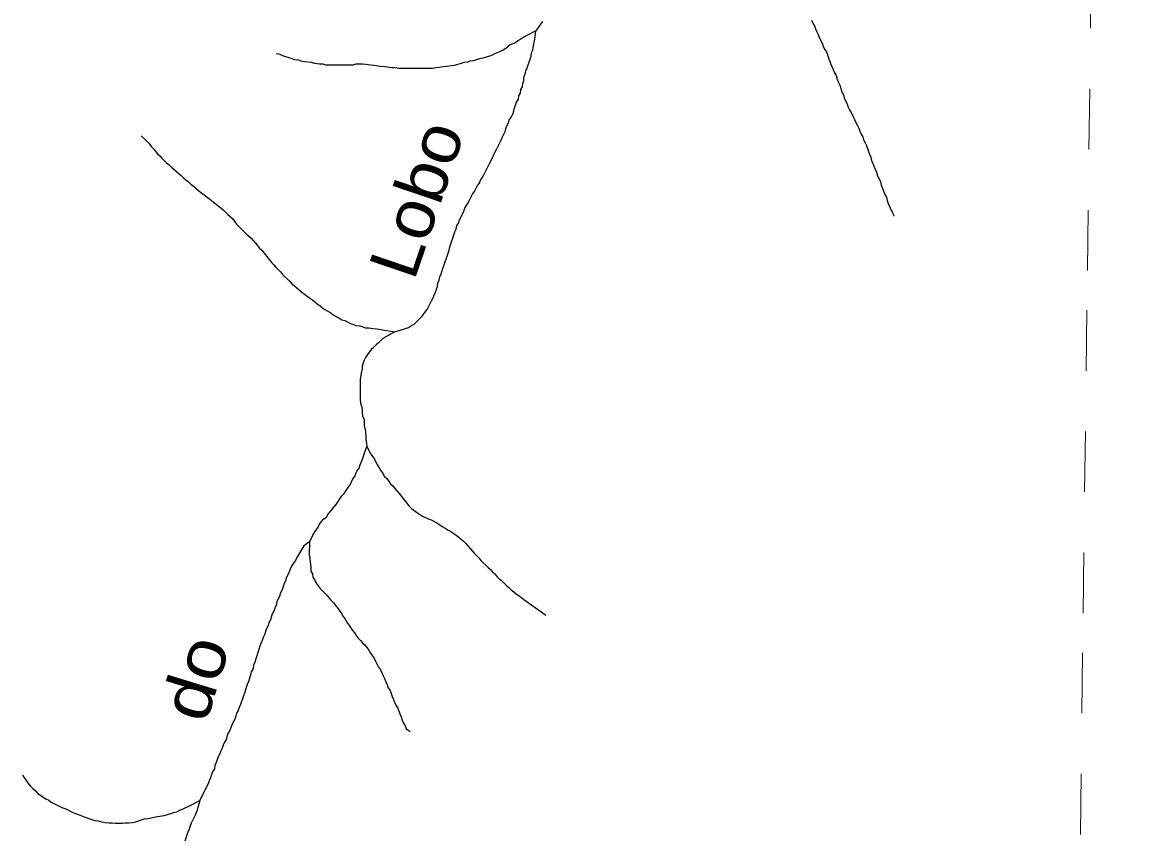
# Model space of a CAD drawing. Extents: x 652.3 to 678, y 7316.9 to 7344.9.
# Drawn here: x 675.947 to 677.802, y 7318.266 to 7319.614 of the extents above; entities that cross this region are included whole.
import ezdxf
from ezdxf.enums import TextEntityAlignment as Align

# ---------------------------------------------------------------- set-up
doc = ezdxf.new("R2010")
doc.units = 0
doc.header["$LTSCALE"] = 0.032
doc.linetypes.add('SHORT_DASHED', pattern=[2.7, 1.5, -1.2])
doc.layers.add('53', color=7, linetype='SHORT_DASHED', lineweight=13)
doc.layers.add('7', color=7, linetype='Continuous', lineweight=25)
doc.layers.add('61', color=7, linetype='Continuous')

msp = doc.modelspace()

# ---------------------------------------------------------------- linework, layer by layer
at = {"layer": '53'}
msp.add_lwpolyline([(677.6746, 7316.9441), (677.6817, 7317.5092), (677.6888, 7318.0742), (677.6959, 7318.6393), (677.703, 7319.2044), (677.7101, 7319.7694), (677.7172, 7320.3345), (677.7242, 7320.8996), (677.7313, 7321.4647), (677.7384, 7322.0297), (677.7455, 7322.5948), (677.7526, 7323.1599), (677.7596, 7323.7249), (677.7667, 7324.29), (677.7738, 7324.8551), (677.7808, 7325.4201), (677.7879, 7325.9852), (677.795, 7326.5503), (677.802, 7327.1153)], dxfattribs=at)
at = {"layer": '7'}
msp.add_line((676.4206, 7318.7344), (676.4214, 7318.7574), dxfattribs=at)
for points in [[(676.8049, 7319.6152), (676.7938, 7319.6001)], [(677.2481, 7319.6176), (677.2505, 7319.6128), (677.2529, 7319.608), (677.2545, 7319.6032), (677.2569, 7319.5985), (677.2593, 7319.5937), (677.2609, 7319.5889), (677.2656, 7319.5794), (677.2672, 7319.5746), (677.2696, 7319.5698), (677.2728, 7319.5651), (677.2744, 7319.5603), (677.276, 7319.5555), (677.2792, 7319.546), (677.2815, 7319.5412), (677.2839, 7319.5364), (677.2855, 7319.5316), (677.2887, 7319.5261), (677.2903, 7319.5205), (677.2919, 7319.5157), (677.2951, 7319.5101), (677.2967, 7319.5046), (677.2982, 7319.499), (677.3006, 7319.4942), (677.3022, 7319.4887), (677.3046, 7319.4839), (677.307, 7319.4791), (677.3086, 7319.4743), (677.311, 7319.4696), (677.3142, 7319.464), (677.3166, 7319.4584), (677.3189, 7319.4537), (677.3213, 7319.4489), (677.3237, 7319.4441), (677.3261, 7319.4393), (677.3277, 7319.4346), (677.3301, 7319.4298), (677.3325, 7319.425), (677.3341, 7319.4202), (677.3364, 7319.4155), (677.3388, 7319.4107), (677.342, 7319.4011), (677.3436, 7319.3964), (677.346, 7319.3916), (677.3468, 7319.386), (677.3492, 7319.3812), (677.3508, 7319.3765), (677.3555, 7319.3669), (677.3571, 7319.3606), (677.3595, 7319.3558), (677.3619, 7319.351), (677.3627, 7319.3454), (677.3651, 7319.3407), (677.3683, 7319.3311), (677.3715, 7319.3255), (677.373, 7319.32), (677.3746, 7319.3152), (677.381, 7319.3009), (677.3836, 7319.2951), (677.3839, 7319.2943)], [(676.7938, 7319.6001), (676.7787, 7319.5921), (676.7739, 7319.5897), (676.7691, 7319.5865), (676.7643, 7319.5834), (676.7604, 7319.5802), (676.7516, 7319.577), (676.7445, 7319.5706), (676.7397, 7319.5682), (676.7301, 7319.5635), (676.7254, 7319.5619), (676.7206, 7319.5595), (676.7158, 7319.5579), (676.7063, 7319.5547), (676.7007, 7319.5539), (676.6911, 7319.5507), (676.6856, 7319.5499), (676.6808, 7319.5483), (676.6752, 7319.5475), (676.6705, 7319.546), (676.6593, 7319.5428), (676.6466, 7319.5412), (676.641, 7319.5404), (676.6346, 7319.5396), (676.6291, 7319.5388), (676.6235, 7319.538), (676.5678, 7319.538), (676.5614, 7319.5388), (676.5559, 7319.5388), (676.5447, 7319.5404), (676.5376, 7319.5412), (676.5264, 7319.5428), (676.5209, 7319.5436), (676.5137, 7319.5444), (676.5081, 7319.5452), (676.497, 7319.5452), (676.4922, 7319.5436), (676.4477, 7319.5436), (676.4429, 7319.5452), (676.4373, 7319.5452), (676.4294, 7319.546), (676.4238, 7319.5475), (676.4126, 7319.5491), (676.4071, 7319.5499), (676.4023, 7319.5515), (676.3967, 7319.5523), (676.392, 7319.5539), (676.3872, 7319.5555), (676.3816, 7319.5571), (676.3768, 7319.5587), (676.3721, 7319.5611), (676.3665, 7319.5619), (676.3661, 7319.5619)], [(676.5614, 7319.1036), (676.5789, 7319.1091), (676.5837, 7319.1107), (676.5885, 7319.1139), (676.5933, 7319.1163), (676.6052, 7319.1282), (676.6148, 7319.1402), (676.6219, 7319.1545), (676.6243, 7319.1593), (676.6259, 7319.164), (676.6283, 7319.1688), (676.6299, 7319.1736), (676.6315, 7319.1783), (676.6323, 7319.1839), (676.6346, 7319.1887), (676.6354, 7319.1943), (676.6378, 7319.199), (676.6394, 7319.2046), (676.641, 7319.2094), (676.6426, 7319.2142), (676.6474, 7319.2285), (676.649, 7319.2332), (676.6506, 7319.238), (676.6522, 7319.2436), (676.6537, 7319.2484), (676.6585, 7319.2627), (676.6601, 7319.2683), (676.6625, 7319.273), (676.6633, 7319.2786), (676.6665, 7319.2834), (676.6681, 7319.2882), (676.6705, 7319.2929), (676.6752, 7319.3025), (676.6768, 7319.3072), (676.6792, 7319.312), (676.6824, 7319.316), (676.6895, 7319.3303), (676.6927, 7319.3351), (676.6975, 7319.3446), (676.7007, 7319.3486), (676.7023, 7319.3534), (676.7055, 7319.3574), (676.7078, 7319.3622), (676.7102, 7319.3669), (676.7174, 7319.3812), (676.7198, 7319.386), (676.7269, 7319.4003), (676.7293, 7319.4051), (676.7365, 7319.4194), (676.7381, 7319.4242), (676.7429, 7319.4338), (676.7445, 7319.4385), (676.746, 7319.4433), (676.7484, 7319.4481), (676.75, 7319.4529), (676.7532, 7319.4576), (676.7556, 7319.4624), (676.7572, 7319.468), (676.7588, 7319.4728), (676.7604, 7319.4775), (676.762, 7319.4823), (676.7651, 7319.4871), (676.7659, 7319.4926), (676.7683, 7319.4974), (676.7691, 7319.503), (676.7715, 7319.5078), (676.7723, 7319.5133), (676.7739, 7319.5181), (676.7739, 7319.5237), (676.7763, 7319.5285), (676.7771, 7319.534), (676.7795, 7319.5388), (676.7842, 7319.5531), (676.7858, 7319.5579), (676.7866, 7319.5635), (676.789, 7319.5682), (676.7906, 7319.5786), (676.7922, 7319.5865), (676.7938, 7319.6001)], [(676.1435, 7319.4268), (676.1438, 7319.4265), (676.1517, 7319.4186), (676.1525, 7319.4178), (676.1564, 7319.4139), (676.1596, 7319.4091), (676.1636, 7319.4051), (676.17, 7319.3972), (676.1739, 7319.394), (676.1771, 7319.39), (676.1811, 7319.386), (676.1851, 7319.382), (676.1891, 7319.3789), (676.193, 7319.3749), (676.197, 7319.3717), (676.201, 7319.3685), (676.205, 7319.3645), (676.209, 7319.3614), (676.2129, 7319.3574), (676.2169, 7319.3542), (676.2209, 7319.351), (676.2249, 7319.347), (676.2296, 7319.3439), (676.2336, 7319.3399), (676.2376, 7319.3367), (676.2416, 7319.3335), (676.2456, 7319.3303), (676.2495, 7319.3271), (676.2543, 7319.324), (676.2583, 7319.3208), (676.2623, 7319.3176), (676.2662, 7319.3144), (676.2702, 7319.3112), (676.2742, 7319.308), (676.2782, 7319.3049), (676.2822, 7319.3009), (676.2861, 7319.2969), (676.2901, 7319.2937), (676.2941, 7319.2897), (676.2973, 7319.285), (676.3005, 7319.281), (676.3124, 7319.2691), (676.3164, 7319.2651), (676.3203, 7319.2619), (676.3243, 7319.2579), (676.3275, 7319.2539), (676.3315, 7319.25), (676.3347, 7319.246), (676.3379, 7319.242), (676.3418, 7319.238), (676.3577, 7319.2181), (676.3617, 7319.2142), (676.3649, 7319.2102), (676.3729, 7319.2022), (676.376, 7319.1982), (676.388, 7319.1863), (676.392, 7319.1823), (676.3959, 7319.1791), (676.3999, 7319.176), (676.4039, 7319.172), (676.4079, 7319.1688), (676.4126, 7319.1656), (676.4166, 7319.1624), (676.4206, 7319.1593), (676.4254, 7319.1561), (676.4294, 7319.1529), (676.4333, 7319.1497), (676.4381, 7319.1465), (676.4421, 7319.1433), (676.4461, 7319.1402), (676.4508, 7319.1378), (676.4556, 7319.1346), (676.4596, 7319.1314), (676.4644, 7319.129), (676.4691, 7319.1266), (676.4739, 7319.1234), (676.4787, 7319.1219), (676.4882, 7319.1171), (676.4978, 7319.1139), (676.5034, 7319.1131), (676.5129, 7319.1099), (676.5185, 7319.1099), (676.5248, 7319.1091), (676.532, 7319.1083), (676.5408, 7319.1067), (676.5614, 7319.1036)], [(676.5614, 7319.1036), (676.5416, 7319.0924), (676.5344, 7319.0853), (676.5304, 7319.0821), (676.5264, 7319.0781), (676.5225, 7319.0741), (676.5161, 7319.0662), (676.5129, 7319.0614), (676.5105, 7319.0566), (676.5073, 7319.0471), (676.5073, 7319.0415), (676.5057, 7319.0359), (676.5042, 7319.0248), (676.5042, 7318.9914), (676.5049, 7318.9858), (676.5065, 7318.981), (676.5073, 7318.9754), (676.5073, 7318.9699), (676.5081, 7318.9643), (676.5105, 7318.9595), (676.5105, 7318.9484), (676.5121, 7318.9428), (676.5137, 7318.9317), (676.5137, 7318.9261), (676.5145, 7318.9197), (676.5153, 7318.9142)], [(676.4214, 7318.7574), (676.4262, 7318.7678), (676.4286, 7318.7725), (676.4317, 7318.7765), (676.4349, 7318.7813), (676.4373, 7318.7861), (676.4405, 7318.7908), (676.4445, 7318.7948), (676.4485, 7318.798), (676.4516, 7318.8028), (676.4548, 7318.8068), (676.458, 7318.8107), (676.4644, 7318.8187), (676.4676, 7318.8235), (676.4707, 7318.8282), (676.4739, 7318.833), (676.4779, 7318.837), (676.4843, 7318.8465), (676.4874, 7318.8513), (676.4922, 7318.8609), (676.4954, 7318.8648), (676.497, 7318.8696), (676.4994, 7318.8744), (676.5026, 7318.8784), (676.5042, 7318.8839), (676.5081, 7318.8935), (676.5105, 7318.9014), (676.5153, 7318.9142)], [(676.5153, 7318.9142), (676.5217, 7318.9014), (676.528, 7318.8935), (676.532, 7318.8839), (676.5352, 7318.8792), (676.5384, 7318.8744), (676.5416, 7318.8704), (676.5439, 7318.8656), (676.5479, 7318.8617), (676.5511, 7318.8577), (676.5543, 7318.8529), (676.5583, 7318.8489), (676.5614, 7318.845), (676.5646, 7318.841), (676.5686, 7318.837), (676.5813, 7318.8211), (676.5845, 7318.8163), (676.5885, 7318.8123), (676.5925, 7318.8091), (676.5972, 7318.806), (676.602, 7318.8028), (676.6068, 7318.7996), (676.6163, 7318.7948), (676.6211, 7318.7932), (676.6307, 7318.7885), (676.6354, 7318.7853), (676.6394, 7318.7821), (676.6442, 7318.7797), (676.649, 7318.7765), (676.6537, 7318.7741), (676.6585, 7318.771), (676.6625, 7318.7678), (676.6665, 7318.7646), (676.6705, 7318.7614), (676.6744, 7318.7582), (676.6784, 7318.7542), (676.6816, 7318.7503), (676.6856, 7318.7463), (676.6919, 7318.7383), (676.6959, 7318.7344), (676.6999, 7318.7304), (676.7031, 7318.7264), (676.715, 7318.7145), (676.719, 7318.7113), (676.7222, 7318.7073), (676.7261, 7318.7041), (676.7293, 7318.7001), (676.7333, 7318.6962), (676.7373, 7318.693), (676.7452, 7318.685), (676.7492, 7318.6818), (676.7532, 7318.6779), (676.7572, 7318.6747), (676.7612, 7318.6715), (676.7651, 7318.6683), (676.7699, 7318.6651), (676.7739, 7318.6619), (676.8017, 7318.6421), (676.8102, 7318.636)], [(676.4214, 7318.7574), (676.4111, 7318.7503), (676.4063, 7318.7423), (676.3999, 7318.7312), (676.3975, 7318.7264), (676.3943, 7318.7216), (676.3912, 7318.7168), (676.3888, 7318.7121), (676.3872, 7318.7073), (676.3848, 7318.7025), (676.3824, 7318.6978), (676.3808, 7318.6922), (676.3784, 7318.6874), (676.3753, 7318.6779), (676.3729, 7318.6731), (676.3713, 7318.6675), (676.3665, 7318.658), (676.3657, 7318.6524), (676.3633, 7318.6476), (676.3617, 7318.6428), (676.3593, 7318.6381), (676.3562, 7318.6285), (676.3538, 7318.6238), (676.3522, 7318.619), (676.3498, 7318.6142), (676.3482, 7318.6094), (676.3466, 7318.6039), (676.3442, 7318.5991), (676.3426, 7318.5943), (676.3402, 7318.5895), (676.3386, 7318.5848), (676.3371, 7318.5792), (676.3355, 7318.5744), (676.3339, 7318.5689), (676.3323, 7318.5641), (676.3307, 7318.5585), (676.3283, 7318.5537), (676.3275, 7318.5482), (676.3243, 7318.5426), (676.3235, 7318.537), (676.3219, 7318.5322), (676.3203, 7318.5267), (676.318, 7318.5219), (676.3132, 7318.5076), (676.3116, 7318.5028), (676.3068, 7318.4885), (676.3044, 7318.4837), (676.3028, 7318.4789), (676.3005, 7318.4742), (676.2989, 7318.4694), (676.2973, 7318.4646), (676.2925, 7318.4551), (676.2909, 7318.4503), (676.2885, 7318.4455), (676.2861, 7318.4407), (676.283, 7318.4312), (676.2806, 7318.4264), (676.2782, 7318.4216), (676.2766, 7318.4169), (676.2742, 7318.4121), (676.2726, 7318.4073), (676.2702, 7318.4026), (676.267, 7318.393), (676.2647, 7318.3882), (676.2639, 7318.3827), (676.2607, 7318.3779), (676.2591, 7318.3731), (676.2575, 7318.3675), (676.2551, 7318.3628), (676.2535, 7318.358), (676.2487, 7318.3484), (676.24, 7318.3301)], [(676.4206, 7318.7344), (676.423, 7318.7145), (676.423, 7318.7089), (676.4254, 7318.7041), (676.4262, 7318.6985), (676.4294, 7318.6938), (676.4317, 7318.689), (676.4349, 7318.6842), (676.4381, 7318.6802), (676.45, 7318.6683), (676.4532, 7318.6643), (676.4564, 7318.6604), (676.4604, 7318.6564), (676.4668, 7318.6484), (676.4731, 7318.6389), (676.4763, 7318.6341), (676.4795, 7318.6293), (676.4819, 7318.6245), (676.4851, 7318.6206), (676.4882, 7318.6158), (676.4914, 7318.611), (676.4946, 7318.607), (676.4978, 7318.6023), (676.501, 7318.5983), (676.5049, 7318.5943), (676.5081, 7318.5903), (676.5121, 7318.5864), (676.5185, 7318.5784), (676.5209, 7318.5736), (676.524, 7318.5696), (676.5272, 7318.5649), (676.5296, 7318.5601), (676.5344, 7318.5505), (676.5376, 7318.5458), (676.54, 7318.541), (676.5423, 7318.5362), (676.5447, 7318.5307), (676.5463, 7318.5259), (676.5487, 7318.5211), (676.5503, 7318.5163), (676.5535, 7318.5116), (676.5551, 7318.5068), (676.5567, 7318.502), (676.5591, 7318.4972), (676.5606, 7318.4925), (676.563, 7318.4877), (676.5662, 7318.4829), (676.5694, 7318.4734), (676.5718, 7318.4686), (676.5734, 7318.463), (676.5758, 7318.4582), (676.5782, 7318.4535), (676.5797, 7318.4487), (676.5861, 7318.4447), (676.5864, 7318.4445)], [(675.9475, 7318.372), (675.9535, 7318.3636), (675.9575, 7318.358), (675.9607, 7318.354), (675.9647, 7318.35), (675.9687, 7318.3461), (675.9726, 7318.3421), (675.9774, 7318.3389), (675.9814, 7318.3357), (675.9862, 7318.3333), (675.9909, 7318.3309), (675.9949, 7318.3278), (676.0092, 7318.3206), (676.014, 7318.3182), (676.0188, 7318.3166), (676.0236, 7318.3142), (676.0283, 7318.3118), (676.0331, 7318.3095), (676.0379, 7318.3079), (676.0427, 7318.3063), (676.0474, 7318.3039), (676.0617, 7318.2991), (676.0665, 7318.2975), (676.0721, 7318.2967), (676.0777, 7318.2951), (676.084, 7318.2943), (676.0896, 7318.2935), (676.0952, 7318.2935), (676.1007, 7318.2927), (676.1119, 7318.2927), (676.1174, 7318.2935), (676.123, 7318.2935), (676.1286, 7318.2943), (676.1342, 7318.2951), (676.1389, 7318.2967), (676.1485, 7318.2999), (676.154, 7318.3007), (676.1596, 7318.3015), (676.1644, 7318.3031), (676.17, 7318.3039), (676.1811, 7318.3055), (676.1922, 7318.3087), (676.197, 7318.3103), (676.2018, 7318.3118), (676.2066, 7318.3142), (676.2137, 7318.3174), (676.2241, 7318.3222), (676.24, 7318.3301)], [(676.24, 7318.3301), (676.2368, 7318.319), (676.2352, 7318.3142), (676.232, 7318.3063), (676.228, 7318.2975), (676.2257, 7318.2927), (676.2225, 7318.2832), (676.2201, 7318.2784), (676.2185, 7318.2736), (676.2169, 7318.2681), (676.2153, 7318.2633)]]:
    msp.add_lwpolyline(points, dxfattribs=at)

# ---------------------------------------------------------------- texts
at = {"layer": '61'}
for s, rotation, width, p in [('Lobo', 71.218, 1.1, (676.6351, 7319.3096)), ('do', 72.913, 1.15, (676.2701, 7318.521))]:
    msp.add_text(s, height=0.08, rotation=rotation, dxfattribs=dict(at, width=width)).set_placement(p, align=Align.CENTER)

doc.saveas('drawing.dxf')
